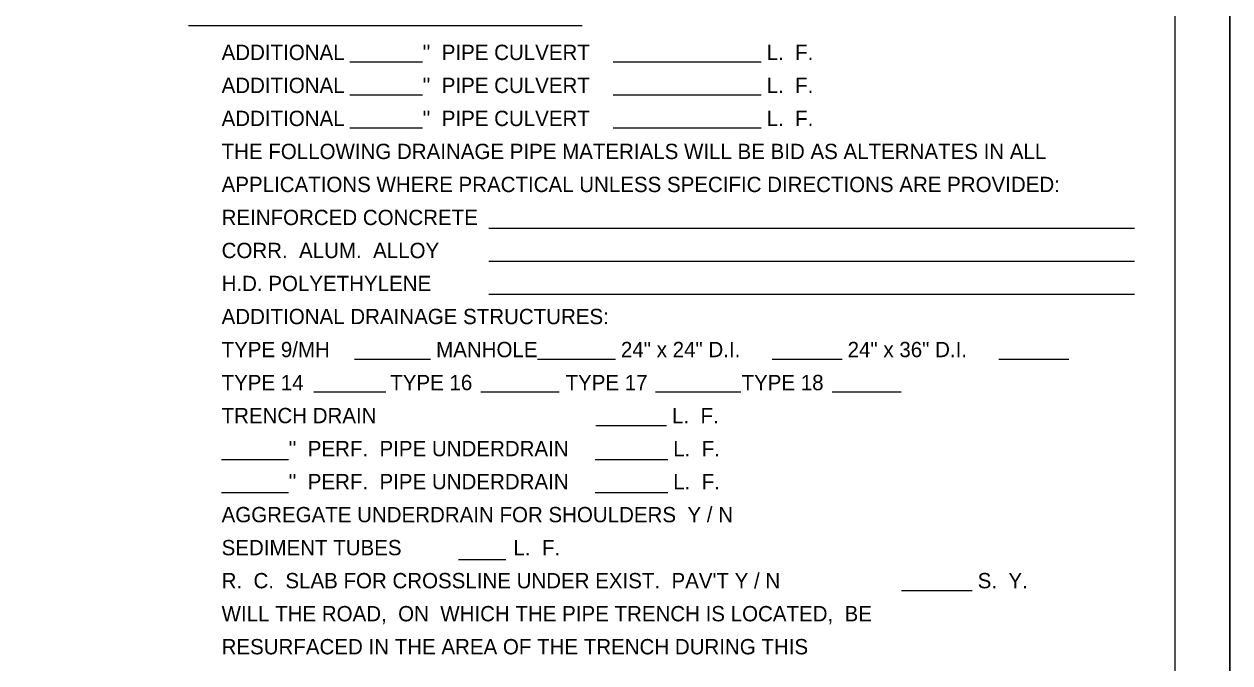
# Model space of a CAD drawing. Extents: x 178032 to 180477, y 178203 to 180757.
# Drawn here: x 179284 to 179831, y 179892 to 180182 of the extents above; entities that cross this region are included whole.
import ezdxf

# ---------------------------------------------------------------- set-up
doc = ezdxf.new("R2010")
doc.units = 0
for name, color, linetype in [('RD_SHT_Bndy', 7, 'Continuous'), ('RD_SHT_IplotShp', 7, 'Continuous'), ('RD_SHT_Snap', 7, 'Continuous'), ('RD_SHT_TX', 7, 'Continuous')]:
    doc.layers.add(name, color=color, linetype=linetype)

msp = doc.modelspace()

# ---------------------------------------------------------------- linework, layer by layer
at = {"layer": 'RD_SHT_Bndy'}
for p, q in [((179806.46, 180705.82), (179806.46, 179656.72)), ((179358.54, 180181.69), (179537.36, 180181.69)), ((179431.87, 180165.2), (179464.87, 180165.2)), ((179551.47, 180165.2), (179618.63, 180165.2)), ((179431.87, 180150.2), (179464.87, 180150.2)), ((179551.47, 180150.2), (179618.63, 180150.2)), ((179431.87, 180135.2), (179464.87, 180135.2)), ((179551.47, 180135.2), (179618.63, 180135.2)), ((179494.92, 180089.61), (179788.21, 180089.61)), ((179494.92, 180074.61), (179788.21, 180074.61)), ((179494.92, 180059.61), (179788.21, 180059.61)), ((179434.05, 180030.09), (179468.46, 180030.09)), ((179517.06, 180030.09), (179552.56, 180030.09)), ((179623.55, 180030.09), (179655.48, 180030.09)), ((179726.47, 180030.09), (179758.4, 180030.09)), ((179415.49, 180015.34), (179448.25, 180015.34)), ((179491.39, 180015.34), (179526.89, 180015.34)), ((179570.58, 180015.34), (179609.35, 180015.34)), ((179650.86, 180015.34), (179682.24, 180015.34)), ((179543.56, 179999.98), (179575.6, 179999.98)), ((179373.64, 179984.51), (179404.04, 179984.51)), ((179543.27, 179984.51), (179576.19, 179984.51)), ((179373.64, 179969.51), (179404.04, 179969.51)), ((179543.27, 179969.51), (179576.19, 179969.51)), ((179481.25, 179939.11), (179502.63, 179939.11)), ((179682.35, 179924.98), (179714.39, 179924.98))]:
    msp.add_line(p, q, dxfattribs=at)
at = {"layer": 'RD_SHT_IplotShp'}
msp.add_lwpolyline([(178035.47, 180731.72), (179831.46, 180731.72), (179831.46, 179631.72), (178035.47, 179631.72)], close=True, dxfattribs=at)
at = {"layer": 'RD_SHT_Snap'}
msp.add_line((179831.46, 179631.72), (179831.46, 180731.72), dxfattribs=at)

# ---------------------------------------------------------------- texts
at = {"layer": 'RD_SHT_TX'}
for s, height, p in [('ADDITIONAL', 6.96, (179373.64, 180166.01)), ("''  PIPE CULVERT", 6.9601, (179464.87, 180166.01)), ('L.  F.', 6.96, (179621.11, 180166.01)), ('ADDITIONAL', 6.96, (179373.64, 180151.01)), ("''  PIPE CULVERT", 6.9601, (179464.87, 180151.01)), ('L.  F.', 6.96, (179621.11, 180151.01)), ('ADDITIONAL', 6.96, (179373.64, 180136.01)), ("''  PIPE CULVERT", 6.9601, (179464.87, 180136.01)), ('L.  F.', 6.96, (179621.11, 180136.01)), ('THE FOLLOWING DRAINAGE PIPE MATERIALS WILL BE BID AS ALTERNATES IN ALL', 6.9601, (179373.64, 180121.01)), ('APPLICATIONS WHERE PRACTICAL UNLESS SPECIFIC DIRECTIONS ARE PROVIDED:', 6.9601, (179373.64, 180106.01)), ('REINFORCED CONCRETE', 6.9601, (179373.64, 180091.01)), ('CORR.  ALUM.  ALLOY', 6.9601, (179373.64, 180076.01)), ('H.D. POLYETHYLENE', 6.9601, (179373.64, 180061.01)), ('ADDITIONAL DRAINAGE STRUCTURES:', 6.9601, (179373.64, 180046.01)), ('TYPE 9/MH', 6.96, (179373.64, 180031.01)), ('MANHOLE', 6.96, (179471.05, 180031.01)), ('24" x 24" D.I.', 6.9601, (179554.97, 180031.01)), ('24" x 36" D.I.', 6.9601, (179657.89, 180031.01)), ('TYPE 14', 6.96, (179373.64, 180016.01)), ('TYPE 16', 6.96, (179450.22, 180016.01)), ('TYPE 17', 6.96, (179529.8, 180016.01)), ('TYPE 18', 6.96, (179609.72, 180016.01)), ('TRENCH DRAIN', 6.9601, (179373.64, 180001.01)), ('L.  F.', 6.96, (179578.15, 180001.01)), ("''  PERF.  PIPE UNDERDRAIN", 6.9601, (179404.04, 179986.01)), ('L.  F.', 6.96, (179578.7, 179986.01)), ("''  PERF.  PIPE UNDERDRAIN", 6.9601, (179404.04, 179971.01)), ('L.  F.', 6.96, (179578.7, 179971.01)), ('AGGREGATE UNDERDRAIN FOR SHOULDERS  Y / N ', 6.9601, (179373.64, 179956.01)), ('SEDIMENT TUBES', 6.9601, (179373.64, 179941.01)), ('L.  F.', 6.96, (179506.14, 179941.01)), ("R.  C.  SLAB FOR CROSSLINE UNDER EXIST.  PAV'T Y / N", 6.9601, (179373.64, 179926.01)), ('S.  Y.', 6.96, (179716.94, 179926.01)), ('WILL THE ROAD,  ON  WHICH THE PIPE TRENCH IS LOCATED,  BE', 6.9601, (179373.64, 179911.01)), ('RESURFACED IN THE AREA OF THE TRENCH DURING THIS', 6.9601, (179373.64, 179896.01))]:
    msp.add_text(s, height=height, dxfattribs=at).set_placement(p)

doc.saveas('drawing.dxf')
